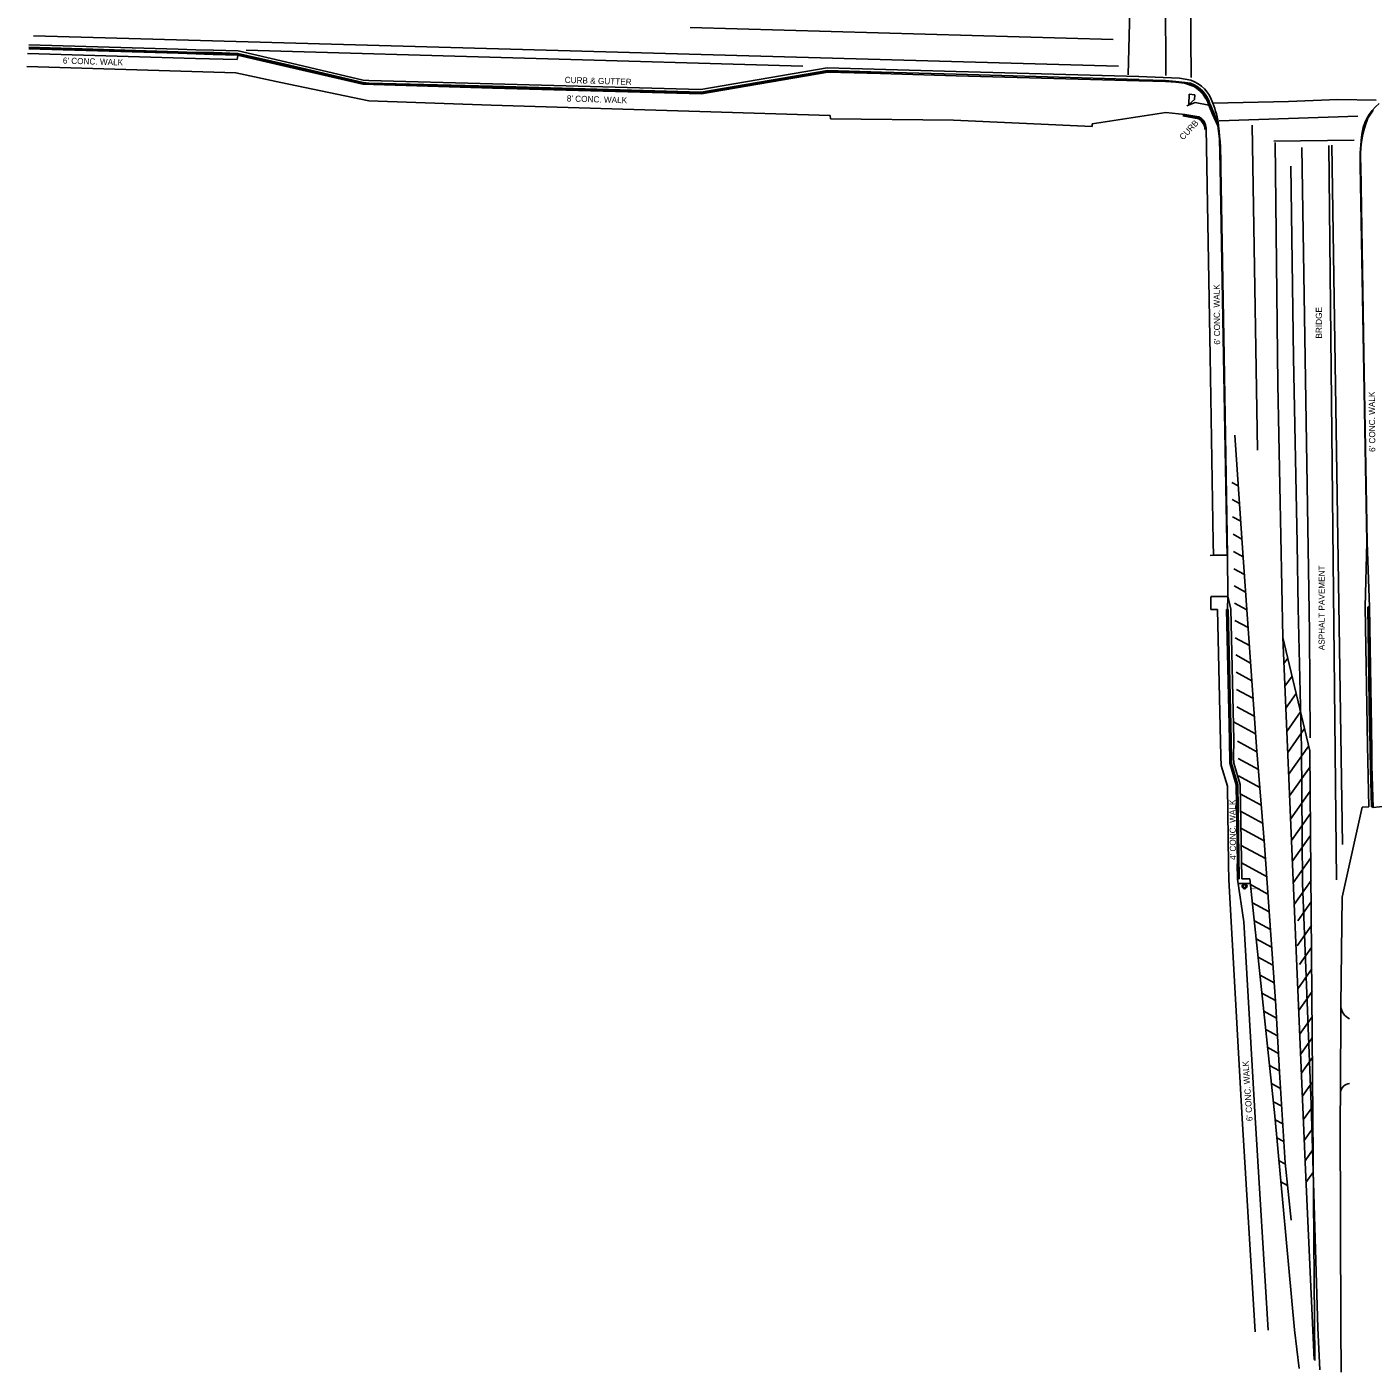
# Model space of a CAD drawing. Extents: x 925226 to 926411, y 852913 to 858733.
# Drawn here: x 925227 to 925841, y 852913 to 853527 of the extents above; entities that cross this region are included whole.
import ezdxf

# ---------------------------------------------------------------- set-up
doc = ezdxf.new("R2010")
doc.units = 0
for name, color, linetype in [('CGep_ep', 7, 'Continuous'), ('CGFace_ep', 7, 'Continuous'), ('CLConst_dp', 7, 'Continuous'), ('ConcSlabs_ep', 7, 'Continuous'), ('CurbRamp_ep', 7, 'Continuous'), ('EndTreat_ep', 7, 'Continuous'), ('ManholeSW_ep', 7, 'Continuous'), ('PavtAsphalt_ep', 7, 'Continuous'), ('PavtConcrete_ep', 7, 'Continuous'), ('PavtCrown_ep', 7, 'Continuous'), ('SidewalkBack_ep', 7, 'Continuous'), ('SidewalkFront_ep', 7, 'Continuous'), ('TextLabel', 7, 'Continuous'), ('XSPt_ep', 7, 'Continuous')]:
    doc.layers.add(name, color=color, linetype=linetype)

# ---------------------------------------------------------------- blocks, each defined once
blk = doc.blocks.new('SSS')
at = {"layer": 'ManholeSW_ep'}
blk.add_line((-2.77, 1.15), (2.77, 1.15), dxfattribs=at)
for radius in [1.15, 0.692]:
    blk.add_circle((0, 0), radius, dxfattribs=at)

msp = doc.modelspace()

# ---------------------------------------------------------------- linework, layer by layer
at = {"layer": 'CGep_ep'}
for p, q in [((925227.38, 853517.37), (925295.54, 853515.31)), ((925295.54, 853515.31), (925303.69, 853514.94)), ((925303.69, 853514.94), (925311.8, 853514.88)), ((925311.8, 853514.88), (925322.87, 853514.53)), ((925322.87, 853514.53), (925344.39, 853509.55)), ((925344.39, 853509.55), (925379.98, 853501.23)), ((925379.98, 853501.23), (925382.62, 853500.89)), ((925382.62, 853500.89), (925439.1, 853499.56)), ((925534.26, 853496.84), (925591.93, 853506.74)), ((925591.93, 853506.74), (925616.58, 853505.91)), ((925616.58, 853505.91), (925650.71, 853505.06)), ((925650.71, 853505.06), (925734.11, 853502.56)), ((925757.74, 853500.92), (925755.09, 853501.27)), ((925439.1, 853499.56), (925534.26, 853496.84)), ((925766.63, 853491.36), (925768.44, 853486.87)), ((925768.44, 853486.87), (925770.55, 853481.47)), ((925839.39, 853206.69), (925838.59, 853261.76)), ((925776.29, 853201.19), (925774.9, 853260.58)), ((925839.78, 853198.59), (925839.39, 853206.69)), ((925776.41, 853190.39), (925776.29, 853201.19)), ((925839.65, 853195.9), (925839.78, 853198.59)), ((925839.81, 853187.9), (925839.65, 853195.9)), ((925779.3, 853180.62), (925776.41, 853190.39)), ((925840.36, 853170.59), (925839.81, 853187.9)), ((925779.91, 853137.71), (925779.3, 853180.62))]:
    msp.add_line(p, q, dxfattribs=at)
msp.add_ellipse((925753.43, 853488.08), major_axis=(-13.54, -0.58), ratio=0.998585, start_param=3.341294, end_param=4.345521, dxfattribs=at)
at = {"layer": 'CGFace_ep'}
for p, q in [((925227.36, 853517.01), (925295.52, 853515.13)), ((925295.52, 853515.13), (925311.78, 853514.56)), ((925311.78, 853514.56), (925322.76, 853514.17)), ((925322.76, 853514.17), (925344.41, 853509.21)), ((925344.41, 853509.21), (925380, 853500.9)), ((925380, 853500.9), (925382.62, 853500.73)), ((925382.62, 853500.73), (925439.17, 853499.19)), ((925534.29, 853496.5), (925592.06, 853506.38)), ((925592.06, 853506.38), (925610.18, 853505.82)), ((925610.18, 853505.82), (925616.59, 853505.77)), ((925740.48, 853502.25), (925746.34, 853502.23)), ((925439.17, 853499.19), (925534.29, 853496.5)), ((925754.34, 853486.52), (925761.56, 853485.15)), ((925839.74, 853206.71), (925838.91, 853261.83)), ((925775.99, 853201.17), (925774.64, 853260.7)), ((925839.95, 853195.91), (925839.74, 853206.71)), ((925775.96, 853193), (925775.99, 853201.17)), ((925840.18, 853189.69), (925839.95, 853195.91)), ((925776.06, 853190.42), (925775.96, 853193)), ((925778.87, 853180.65), (925776.06, 853190.42)), ((925840.61, 853170.58), (925840.18, 853189.69)), ((925779.58, 853144.75), (925778.87, 853180.65)), ((925779.73, 853137.73), (925779.58, 853144.75))]:
    msp.add_line(p, q, dxfattribs=at)
for centre, major_axis, ratio, start_param, end_param in [((925751.14, 853486.57), (-12.95, 10.23), 0.955175, 4.126785, 4.795921), ((925758.22, 853479.6), (-4.38, -4.76), 0.999544, 2.42348, 3.344542)]:
    msp.add_ellipse(centre, major_axis=major_axis, ratio=ratio, start_param=start_param, end_param=end_param, dxfattribs=at)
at = {"layer": 'ConcSlabs_ep'}
for p, q in [((925757.16, 853495.89), (925757, 853491.2)), ((925759.71, 853495.68), (925757.16, 853495.89)), ((925759.58, 853493.47), (925759.71, 853495.68)), ((925757, 853491.2), (925759.58, 853493.47)), ((925774.57, 853285.49), (925766.62, 853285.35)), ((925774.57, 853285.49), (925774.82, 853266.71)), ((925774.82, 853266.71), (925767, 853266.55))]:
    msp.add_line(p, q, dxfattribs=at)
at = {"layer": 'CurbRamp_ep'}
for p, q in [((925740.48, 853502.25), (925734.26, 853502.54)), ((925740.44, 853501.83), (925734.28, 853502.01)), ((925746.28, 853501.64), (925750.98, 853501.35)), ((925746.34, 853502.23), (925751.07, 853501.74)), ((925750.98, 853501.35), (925754.93, 853500.9)), ((925751.07, 853501.74), (925755.09, 853501.27)), ((925754.93, 853500.9), (925759.34, 853499.39)), ((925755.09, 853501.27), (925759.8, 853499.75)), ((925759.85, 853492.12), (925755.98, 853490.58)), ((925766.13, 853490.95), (925759.85, 853492.12)), ((925767.82, 853486.76), (925766.13, 853490.95)), ((925770.24, 853481.49), (925767.82, 853486.76))]:
    msp.add_line(p, q, dxfattribs=at)
at = {"layer": 'EndTreat_ep'}
for p, q in [((925746.46, 853504.49), (925745.81, 853636.38)), ((925756.83, 853636.13), (925757.98, 853503.54)), ((925729.28, 853504.82), (925731.08, 853580.21)), ((925722.43, 853520.94), (925529.35, 853526.32)), ((925724.77, 853508.75), (925229.47, 853522.57)), ((925326.59, 853515.99), (925580.68, 853508.7)), ((925770.85, 853483.71), (925834.12, 853485.95)), ((925785.93, 853481.73), (925788.31, 853333.32)), ((925795.69, 853474.41), (925832.35, 853474.97)), ((925797.58, 853363.59), (925796.34, 853473.88)), ((925808.6, 853471.63), (925812.08, 853250.2)), ((925824.37, 853137.25), (925820.88, 853472.48)), ((925822.19, 853472.66), (925827.04, 853153.39)), ((925799.86, 853247.9), (925797.58, 853363.59)), ((925777.89, 853340.18), (925781.62, 853286.56)), ((925776.59, 853318.69), (925779.5, 853317.1)), ((925776.76, 853310.81), (925780.06, 853309.01)), ((925776.94, 853302.93), (925780.62, 853300.92)), ((925777.12, 853295.05), (925781.19, 853292.83)), ((925777.29, 853287.17), (925781.75, 853284.74)), ((925781.62, 853286.56), (925787.86, 853198.03)), ((925777.47, 853279.29), (925782.32, 853276.65)), ((925777.64, 853271.41), (925782.89, 853268.55)), ((925777.82, 853263.53), (925783.46, 853260.46)), ((925777.99, 853255.65), (925784.03, 853252.37)), ((925812.08, 853250.2), (925812.33, 853202.02)), ((925778.17, 853247.77), (925784.6, 853244.27)), ((925812.22, 853196.16), (925799.86, 853247.9)), ((925799.86, 853247.9), (925810.15, 853004.86)), ((925778.34, 853239.89), (925785.17, 853236.18)), ((925802.11, 853238.51), (925800.36, 853236.03)), ((925778.52, 853232.01), (925785.74, 853228.08)), ((925804.08, 853230.23), (925800.81, 853225.58)), ((925778.69, 853224.13), (925786.1, 853220.11)), ((925805.97, 853222.35), (925801.23, 853215.62)), ((925778.87, 853216.26), (925786.75, 853211.97)), ((925807.98, 853213.91), (925801.68, 853204.95)), ((925777.34, 853209.3), (925787.4, 853203.83)), ((925809.79, 853206.33), (925802.09, 853195.37)), ((925779.22, 853200.5), (925788.05, 853195.7)), ((925787.86, 853198.03), (925791.45, 853153.02)), ((925811.69, 853198.39), (925802.51, 853185.34)), ((925814.51, 852917.82), (925812.22, 853196.16)), ((925779.4, 853192.62), (925788.7, 853187.56)), ((925812.28, 853188.89), (925802.92, 853175.59)), ((925779.57, 853184.74), (925789.35, 853179.42)), ((925780.43, 853176.49), (925789.99, 853171.28)), ((925812.37, 853177.71), (925803.37, 853164.92)), ((925780.57, 853168.63), (925790.64, 853163.15)), ((925812.46, 853167.55), (925803.79, 853155.22)), ((925780.7, 853160.77), (925791.29, 853155.01)), ((925812.54, 853157.42), (925804.19, 853145.55)), ((925780.84, 853152.91), (925791.88, 853146.91)), ((925791.45, 853153.02), (925796.63, 853079.72)), ((925780.97, 853145.06), (925792.45, 853138.81)), ((925812.62, 853147.35), (925804.6, 853135.94)), ((925785.1, 853135.03), (925793.03, 853130.72)), ((925812.82, 853137), (925805.03, 853125.91)), ((925785.98, 853126.77), (925793.6, 853122.62)), ((925812.79, 853127.15), (925806.67, 853118.45)), ((925786.85, 853118.51), (925794.17, 853114.53)), ((925812.88, 853116.42), (925806.36, 853107.15)), ((925787.72, 853110.25), (925794.74, 853106.43)), ((925788.59, 853101.99), (925795.32, 853098.34)), ((925812.96, 853106.38), (925807.46, 853098.57)), ((925813.04, 853096.55), (925806.64, 853087.45)), ((925789.46, 853093.74), (925795.89, 853090.24)), ((925790.33, 853085.48), (925796.46, 853082.15)), ((925813.32, 853086.25), (925807.08, 853077.38)), ((925791.2, 853077.22), (925796.96, 853074.09)), ((925796.63, 853079.72), (925798.41, 853049.36)), ((925813.22, 853074.7), (925807.54, 853066.62)), ((925792.08, 853068.96), (925797.43, 853066.05)), ((925813.3, 853065.13), (925807.92, 853057.49)), ((925792.95, 853060.71), (925797.9, 853058.01)), ((925793.82, 853052.45), (925798.37, 853049.97)), ((925813.37, 853056.08), (925808.29, 853048.85)), ((925798.41, 853049.36), (925800.95, 853007.96)), ((925794.69, 853044.19), (925798.86, 853041.92)), ((925813.46, 853045.02), (925808.72, 853038.28)), ((925795.56, 853035.93), (925799.36, 853033.87)), ((925813.56, 853033.83), (925809.19, 853027.62)), ((925796.41, 853027.69), (925799.85, 853025.81)), ((925813.64, 853023.99), (925809.58, 853018.23)), ((925797.16, 853019.5), (925800.35, 853017.76)), ((925813.72, 853014.22), (925809.98, 853008.9)), ((925798.11, 853009.02), (925801, 853007.45)), ((925800.95, 853007.96), (925803.61, 852981.91)), ((925810.15, 853004.86), (925814.18, 852918.23)), ((925813.8, 853003.94), (925810.42, 852999.13)), ((925799, 852999.29), (925802, 852997.66))]:
    msp.add_line(p, q, dxfattribs=at)
at = {"layer": 'PavtAsphalt_ep'}
for p, q in [((925295.65, 853516.49), (925227.37, 853518.52)), ((925303.65, 853516.15), (925295.65, 853516.49)), ((925311.64, 853515.94), (925303.65, 853516.15)), ((925322.98, 853515.69), (925311.64, 853515.94)), ((925344.55, 853510.71), (925322.98, 853515.69)), ((925380.1, 853502.35), (925344.55, 853510.71)), ((925591.8, 853507.93), (925534.21, 853498.08)), ((925650.77, 853506.33), (925591.8, 853507.93)), ((925382.69, 853502.15), (925380.1, 853502.35)), ((925439.05, 853500.68), (925382.69, 853502.15)), ((925734.16, 853504.02), (925650.77, 853506.33)), ((925752.75, 853503.28), (925734.16, 853504.02)), ((925757.85, 853502.32), (925752.75, 853503.28)), ((925534.21, 853498.08), (925439.05, 853500.68)), ((925802.47, 853492.52), (925767.85, 853491.88)), ((925824.99, 853493.51), (925802.47, 853492.52)), ((925842.5, 853493.23), (925824.99, 853493.51)), ((925776.15, 853260.74), (925774.82, 853266.71)), ((925838.52, 853198.53), (925837.48, 853261.88)), ((925777.53, 853201.1), (925776.15, 853260.74)), ((925777.38, 853193.04), (925777.53, 853201.1)), ((925838.52, 853198.53), (925839.18, 853170.55)), ((925777.53, 853190.53), (925777.38, 853193.04)), ((925780.36, 853180.75), (925777.53, 853190.53)), ((925781.1, 853137.7), (925780.36, 853180.75)), ((925826.91, 853129.39), (925836.13, 853170.39)), ((925839.18, 853170.55), (925836.13, 853170.39)), ((925784.83, 853137.67), (925781.1, 853137.7)), ((925796.25, 853029.44), (925784.83, 853137.67)), ((925826.31, 853080), (925826.91, 853129.39)), ((925826.12, 853040.31), (925826.31, 853080)), ((925825.96, 853027.95), (925826.12, 853040.31)), ((925805.18, 852931.73), (925796.25, 853029.44)), ((925826.26, 852933.28), (925825.96, 853027.95)), ((925807.24, 852914.16), (925805.18, 852931.73)), ((925826.45, 852912.51), (925826.26, 852933.28))]:
    msp.add_line(p, q, dxfattribs=at)
for centre, major_axis, ratio, start_param, end_param in [((925752.68, 853487.39), (15.51, -3.13), 0.998045, 0.487335, 1.436508), ((925833.36, 853080.13), (2.77, 6.49), 0.999224, 1.992383, 3.103839), ((925830.83, 853039.55), (-4.76, -0.09), 0.999924, 4.822988, 6.104144)]:
    msp.add_ellipse(centre, major_axis=major_axis, ratio=ratio, start_param=start_param, end_param=end_param, dxfattribs=at)
at = {"layer": 'PavtConcrete_ep'}
for p, q in [((925770.55, 853481.47), (925770.48, 853481.73)), ((925771.1, 853474.67), (925770.55, 853481.47)), ((925835.1, 853469.11), (925835.79, 853476.24)), ((925771.49, 853462.43), (925771.1, 853474.67)), ((925835.19, 853463.45), (925835.1, 853469.11)), ((925773.04, 853376.32), (925771.49, 853462.43)), ((925773.04, 853376.32), (925771.49, 853462.43)), ((925836.66, 853377.7), (925835.19, 853463.45)), ((925774.57, 853285.49), (925773.04, 853376.32)), ((925774.57, 853285.49), (925773.04, 853376.32)), ((925838.23, 853291.33), (925836.66, 853377.7)), ((925837.48, 853261.88), (925838.23, 853291.33))]:
    msp.add_line(p, q, dxfattribs=at)
for centre, major_axis, ratio, start_param, end_param in [((925733.31, 853477.49), (-5.5, 37.15), 0.995996, 4.679113, 4.959329), ((925731.84, 853476.94), (-7.81, 38.48), 0.992572, 4.629172, 4.904114), ((925856.96, 853474.93), (-11.32, -17.95), 0.998932, 4.369426, 5.21253), ((925623.32, 853464.67), (-4.54, 148.31), 0.998686, 4.666276, 4.795246)]:
    msp.add_ellipse(centre, major_axis=major_axis, ratio=ratio, start_param=start_param, end_param=end_param, dxfattribs=at)
at = {"layer": 'PavtCrown_ep'}
for p, q in [((925803.45, 853463.09), (925804.69, 853375.63)), ((925804.69, 853375.63), (925806.41, 853290.85)), ((925806.41, 853290.85), (925806.89, 853261.25)), ((925808.34, 853197.42), (925806.89, 853261.25)), ((925808.78, 853135.69), (925808.34, 853197.42)), ((925812.86, 853034.77), (925808.78, 853135.69)), ((925815.77, 852932.75), (925812.86, 853034.77)), ((925816.7, 852913.54), (925815.77, 852932.75))]:
    msp.add_line(p, q, dxfattribs=at)
at = {"layer": 'SidewalkBack_ep'}
for p, q in [((925226.53, 853508.6), (925301.85, 853506.34)), ((925301.85, 853506.34), (925321.93, 853505.7)), ((925321.93, 853505.7), (925342.39, 853501.24)), ((925342.39, 853501.24), (925382.55, 853492.89)), ((925382.55, 853492.89), (925438.53, 853490.9)), ((925438.53, 853490.9), (925533.68, 853488.01)), ((925533.68, 853488.01), (925593.25, 853486.2)), ((925593.25, 853486.2), (925593.34, 853484.64)), ((925593.34, 853484.64), (925649.52, 853484.12)), ((925649.52, 853484.12), (925712.76, 853481.12)), ((925712.76, 853481.12), (925712.86, 853482.37)), ((925712.86, 853482.37), (925746.52, 853487.48)), ((925746.52, 853487.48), (925755.19, 853486.57)), ((925755.19, 853486.57), (925761.52, 853485.55)), ((925766.63, 853376.3), (925764.8, 853480.39)), ((925768.07, 853291.4), (925766.63, 853376.3)), ((925768.07, 853291.4), (925768.26, 853285.52)), ((925768.26, 853285.52), (925774.5, 853285.58)), ((925766.99, 853266.46), (925774.71, 853266.61)), ((925767.06, 853260.59), (925766.99, 853266.46)), ((925770.09, 853260.64), (925767.06, 853260.59)), ((925771.62, 853193.49), (925770.09, 853260.64)), ((925771.72, 853189.47), (925771.62, 853193.49)), ((925774.57, 853179.99), (925771.72, 853189.47)), ((925775.07, 853144.22), (925774.57, 853179.99)), ((925846.89, 853170.87), (925841.05, 853170.33)), ((925775.24, 853137.3), (925775.07, 853144.22)), ((925781.26, 853028.34), (925775.24, 853137.3)), ((925787.19, 852930.92), (925781.26, 853028.34))]:
    msp.add_line(p, q, dxfattribs=at)
msp.add_ellipse((925759.34, 853480.58), major_axis=(3.68, -4.09), ratio=0.985003, start_param=0.812119, end_param=1.990274, dxfattribs=at)
at = {"layer": 'SidewalkFront_ep'}
for p, q in [((925226.84, 853514.52), (925303.44, 853512.28)), ((925322.57, 853511.69), (925322.75, 853513.58)), ((925303.44, 853512.28), (925322.57, 853511.69)), ((925838.43, 853484.52), (925841.05, 853488.64)), ((925770.93, 853475.37), (925770.24, 853481.49)), ((925771.27, 853462.4), (925770.93, 853475.37)), ((925772.78, 853376.29), (925771.27, 853462.4)), ((925835.46, 853463.42), (925836.88, 853377.6)), ((925774.24, 853291.47), (925772.78, 853376.29)), ((925836.88, 853377.6), (925838.41, 853291.3)), ((925774.5, 853285.58), (925774.24, 853291.47)), ((925839.49, 853261.88), (925838.41, 853291.3)), ((925774.71, 853266.61), (925774.64, 853260.83)), ((925779.21, 853137.5), (925778.98, 853144.53)), ((925782.04, 853118), (925779.21, 853137.5)), ((925787.18, 853028.68), (925782.04, 853118)), ((925793.22, 852931.6), (925787.18, 853028.68))]:
    msp.add_line(p, q, dxfattribs=at)
msp.add_ellipse((925884.9, 853467.21), major_axis=(9.28, -48.72), ratio=0.999656, start_param=4.167804, end_param=4.600687, dxfattribs=at)
at = {"layer": 'XSPt_ep'}
for p, q in [((925227.35, 853516.59), (925295.63, 853514.6)), ((925295.63, 853514.6), (925311.54, 853514.01)), ((925311.54, 853514.01), (925322.66, 853513.72)), ((925322.66, 853513.72), (925344.26, 853508.72)), ((925344.26, 853508.72), (925379.94, 853500.42)), ((925534.47, 853496.11), (925592.16, 853505.97)), ((925592.16, 853505.97), (925610.17, 853505.47)), ((925610.17, 853505.47), (925616.23, 853505.36)), ((925616.23, 853505.36), (925650.74, 853504.33)), ((925650.74, 853504.33), (925734.28, 853502.01)), ((925740.44, 853501.83), (925746.28, 853501.64)), ((925379.94, 853500.42), (925439.12, 853498.66)), ((925439.12, 853498.66), (925534.47, 853496.11)), ((925754.27, 853486.07), (925761.49, 853484.7)), ((925838.91, 853261.83), (925838.59, 853261.76)), ((925839.49, 853261.88), (925838.91, 853261.83)), ((925840.26, 853206.7), (925839.49, 853261.88)), ((925775.48, 853201.12), (925774.19, 853260.73)), ((925774.19, 853260.73), (925774.64, 853260.7)), ((925774.64, 853260.7), (925774.9, 853260.58)), ((925840.46, 853196.01), (925840.26, 853206.7)), ((925775.61, 853190.44), (925775.48, 853201.12)), ((925840.55, 853189.24), (925840.46, 853196.01)), ((925778.53, 853180.6), (925775.61, 853190.44)), ((925841.05, 853170.33), (925840.55, 853189.24)), ((925779.1, 853144.63), (925778.53, 853180.6)), ((925840.61, 853170.58), (925840.36, 853170.59)), ((925841.05, 853170.33), (925840.61, 853170.58)), ((925779.29, 853137.73), (925779.1, 853144.63)), ((925779.29, 853137.73), (925779.73, 853137.73)), ((925779.73, 853137.73), (925779.91, 853137.71))]:
    msp.add_line(p, q, dxfattribs=at)
for centre, major_axis, ratio, start_param, end_param in [((925751.16, 853486.34), (-12.86, 9.93), 0.948026, 4.122986, 4.804968), ((925757.84, 853479.37), (5.79, -2.89), 0.999106, 0.532659, 1.432423)]:
    msp.add_ellipse(centre, major_axis=major_axis, ratio=ratio, start_param=start_param, end_param=end_param, dxfattribs=at)

# ---------------------------------------------------------------- block references
at = {"layer": 'ManholeSW_ep'}
msp.add_blockref('SSS', (925782.37, 853134.34), dxfattribs=at)

# ---------------------------------------------------------------- texts
at = {"layer": 'CLConst_dp'}
msp.add_text('SPEED LIMIT', height=0.5, dxfattribs=at).set_placement((925785.14, 853132.83))
at = {"layer": 'TextLabel'}
for s, rotation, p in [("6' CONC. WALK", 358.17244, (925242.88, 853509.9)), ('CURB & GUTTER', 358.17244, (925472, 853501.08)), ("8' CONC. WALK", 358.17244, (925472.95, 853492.6)), ('CURB', 47.05066, (925754.39, 853474.78)), ("6' CONC. WALK", 90.50606, (925771.25, 853381.57)), ('BRIDGE', 90.01403, (925817.72, 853384.37)), ("6' CONC. WALK", 90.50606, (925842.08, 853332.6)), ('ASPHALT PAVEMENT', 90.01403, (925818.96, 853242.06)), ("4' CONC. WALK", 90.50606, (925778.49, 853146.32)), ("6' CONC. WALK", 93.99133, (925786.09, 853027.15))]:
    msp.add_text(s, height=2.8, rotation=rotation, dxfattribs=at).set_placement(p)

doc.saveas('drawing.dxf')
